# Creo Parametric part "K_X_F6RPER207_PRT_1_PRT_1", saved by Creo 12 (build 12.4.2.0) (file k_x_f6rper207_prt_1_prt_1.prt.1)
Units: Custom; MM, KILOGRAM, SECS

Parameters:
  PTC_WM_ITERATION = "0"
  PTC_WM_VERSION = "-.0"
  PTC_WM_LIFECYCLE_STATE = "In Work"
  PTC_WM_LIFECYCLE = "MO_CADDocument"
  PTC_WM_CREATED_BY = "Maximilian Roepper (Z0017RMS: MO)"
  PTC_WM_CREATED_ON = "18-Sep-26 11:36:42 AM"
  PTC_WM_MODIFIED_BY = "Maximilian Roepper (Z0017RMS: MO)"
  PTC_WM_MODIFIED_ON = "18-Sep-26 11:36:46 AM"
  PDMLINKNUMBER = "PDM000071455058"
  PTC_WM_NAME = "k_x_f6rper207_prt_1_prt_1.prt"
  PTC_WM_NUMBER = "PDM000071455058"

Other parameters: WEIGHT, WEIGHT_FACTOR, WEIGHT_ADD, _MASS_TEMP, _DIFF_TEMP, MC_ERRORS, SUPPLIER

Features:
  1. coordinate system
  2. datum plane "PRT_YZ"
  3. datum plane "PRT_XY"
  4. datum plane "PRT_XZ"
  5. coordinate system
  6. datum axis
  7. datum axis
  8. datum axis
  9. coordinate system
  10. imported feature
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
Other named items: PRT, SIEMENS_MO, DRW_VIEW_ORG, PRT_X, PRT_Y, PRT_Z, CS0, ROUGH_GROB

Layers: 00_STD_CSYS-KSYS, 01_STD_PLANES-EBENEN, 02_STD_AXES-ACHSEN, 03_STD_CSYS-KSYS, 24_IMPORT_FEAT-IMPORT_KE

Surfaces: 16 plane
